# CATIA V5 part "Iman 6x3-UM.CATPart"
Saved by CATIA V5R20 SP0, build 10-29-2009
Part number: Iman 6x3-UM
Revision: ANY
Definition: UNKNOWN
Nomenclature: Iman 6x3-UM
Source: Unknown
Bounding box of the stored display mesh (mm): x -3 to 3, y -2.853 to 2.853, z 0 to 3
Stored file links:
  C:\Users\Utente\Desktop\IO LAVORO\3D X SITO CF\X SITO\3D files UM\UM064242 PRODUCT\Iman 6x3-UM.CATPart
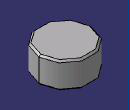
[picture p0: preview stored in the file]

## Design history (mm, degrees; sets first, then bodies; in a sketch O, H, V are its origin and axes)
Body1 "Chaflán1" (main body)
  Solid1: solid without history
